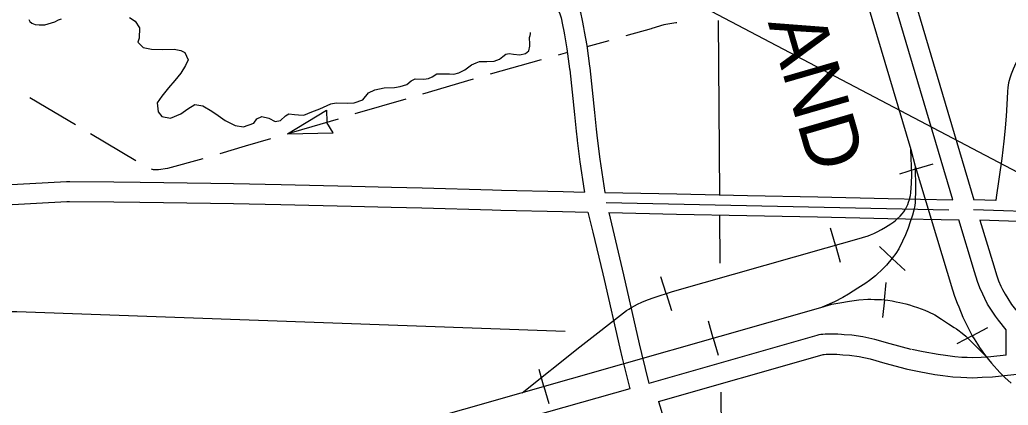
# Model space of a CAD drawing. Extents: x 1373094 to 1376427, y 1168361 to 1170494.
# Drawn here: x 1373679.1 to 1373802.5, y 1170075.4 to 1170123.5 of the extents above; entities that cross this region are included whole.
import ezdxf

# ---------------------------------------------------------------- set-up
doc = ezdxf.new("R2010")
doc.units = 0
doc.layers.add('R_Axis', color=7, linetype='Continuous')
doc.layers.add('R_Draft', color=7, linetype='Continuous')

msp = doc.modelspace()

# ---------------------------------------------------------------- linework, layer by layer
at = {"layer": 'R_Axis'}
for p, q in [((1373712.5, 1170109.25), (1373717.38, 1170112.23)), ((1373717.38, 1170112.23), (1373717.42, 1170110.71)), ((1373718.22, 1170109.39), (1373717.43, 1170110.69)), ((1373712.5, 1170109.25), (1373718.22, 1170109.39)), ((1373791.02, 1170104.89), (1373788.92, 1170104.25)), ((1373791.02, 1170104.89), (1373793.13, 1170105.52)), ((1373780.95, 1170095.36), (1373780.34, 1170097.48)), ((1373780.95, 1170095.36), (1373781.55, 1170093.25)), ((1373788.04, 1170093.7), (1373786.43, 1170095.2)), ((1373789.66, 1170092.21), (1373788.04, 1170093.7)), ((1373759.79, 1170089.32), (1373759.12, 1170091.41)), ((1373787.05, 1170088.54), (1373787.27, 1170090.73)), ((1373759.79, 1170089.32), (1373760.46, 1170087.22)), ((1373787.05, 1170088.54), (1373786.82, 1170086.35)), ((1373765.69, 1170083.77), (1373765.09, 1170085.89)), ((1373798.03, 1170084.07), (1373799.97, 1170085.1)), ((1373765.69, 1170083.77), (1373766.29, 1170081.66)), ((1373798.03, 1170084.07), (1373796.08, 1170083.05)), ((1373744.54, 1170077.73), (1373743.93, 1170079.85)), ((1373744.54, 1170077.73), (1373745.14, 1170075.62))]:
    msp.add_line(p, q, dxfattribs=at)
for points in [[(1373784.43, 1170127.18), (1373790.37, 1170107.3), (1373790.91, 1170105.25), (1373795.57, 1170089.79), (1373795.81, 1170089), (1373796.14, 1170088.13), (1373796.33, 1170087.66), (1373796.87, 1170086.38), (1373797.01, 1170086.06), (1373797.28, 1170085.54), (1373797.46, 1170085.16), (1373798.07, 1170083.99), (1373798.25, 1170083.68), (1373798.67, 1170083), (1373798.94, 1170082.6), (1373799.26, 1170082.14), (1373799.57, 1170081.73), (1373800.07, 1170081.1), (1373800.45, 1170080.64), (1373801.48, 1170079.47), (1373801.76, 1170079.18), (1373802.08, 1170078.87), (1373802.87, 1170078.17)], [(1373784.43, 1170127.18), (1373790.37, 1170107.3), (1373790.91, 1170105.25), (1373795.57, 1170089.79), (1373795.81, 1170089), (1373796.14, 1170088.13), (1373796.33, 1170087.66), (1373796.87, 1170086.38), (1373797.01, 1170086.06), (1373797.28, 1170085.54), (1373797.46, 1170085.16), (1373798.07, 1170083.99), (1373798.25, 1170083.68), (1373798.67, 1170083), (1373798.94, 1170082.6), (1373799.26, 1170082.14), (1373799.57, 1170081.73), (1373800.07, 1170081.1), (1373800.45, 1170080.64), (1373801.48, 1170079.47), (1373801.76, 1170079.18), (1373802.08, 1170078.87), (1373802.87, 1170078.17)], [(1373795.6, 1170101.04), (1373788, 1170126.75)], [(1373790.4, 1170127.45), (1373798.21, 1170101.02)], [(1373748.16, 1170126.5), (1373748.57, 1170125.75), (1373748.85, 1170125.14), (1373749.09, 1170124.39), (1373749.31, 1170123.4), (1373749.48, 1170122.55), (1373749.56, 1170122.05), (1373749.88, 1170120.28), (1373750.24, 1170117.69), (1373750.25, 1170117.51)], [(1373745.97, 1170125.3), (1373746.34, 1170124.63), (1373746.51, 1170124.24), (1373746.68, 1170123.74), (1373746.86, 1170122.88), (1373747.02, 1170122.09), (1373747.1, 1170121.63), (1373747.41, 1170119.89), (1373747.75, 1170117.38), (1373747.77, 1170117.24)], [(1373680.22, 1170123.53), (1373680.34, 1170123.28), (1373680.6, 1170123.07), (1373681, 1170122.92), (1373681.5, 1170122.87), (1373682.22, 1170122.87), (1373683.45, 1170123.23), (1373683.93, 1170123.48), (1373684.29, 1170123.62)], [(1373692.77, 1170123.78), (1373693.51, 1170123.33), (1373694.05, 1170122.51), (1373693.98, 1170121.19), (1373693.81, 1170120.69), (1373694.49, 1170120.02), (1373695.51, 1170119.84), (1373696.93, 1170119.8), (1373698.36, 1170119.84), (1373699.18, 1170119.66), (1373699.69, 1170119.4), (1373700.1, 1170118.51), (1373699.77, 1170117.78), (1373699.18, 1170116.84), (1373698.44, 1170115.9), (1373697.67, 1170114.99), (1373696.82, 1170113.98), (1373696.25, 1170113.13), (1373696.38, 1170112), (1373696.83, 1170111.43), (1373697.92, 1170111.24), (1373699.2, 1170111.77), (1373700.08, 1170112.38), (1373700.95, 1170112.91), (1373701.96, 1170112.75), (1373703.05, 1170112.1), (1373703.86, 1170111.54), (1373704.73, 1170110.93), (1373705.96, 1170110.3), (1373707.03, 1170110.13), (1373708.3, 1170110.61), (1373708.7, 1170111.15), (1373709.29, 1170111.42), (1373710.18, 1170111.23), (1373710.97, 1170110.79), (1373711.65, 1170110.91), (1373712.25, 1170111.51), (1373712.69, 1170111.78), (1373713.37, 1170111.66), (1373713.87, 1170111.63), (1373714.55, 1170111.59), (1373715.54, 1170112.01), (1373716.54, 1170112.38), (1373717.94, 1170113), (1373718.6, 1170113.12), (1373719.98, 1170113.1), (1373720.83, 1170113.14), (1373721.92, 1170113.51), (1373722.64, 1170114.38), (1373723.41, 1170114.77), (1373724.57, 1170115.02), (1373725.86, 1170115.06), (1373726.58, 1170115.17), (1373727.4, 1170115.43), (1373727.97, 1170115.89), (1373728.44, 1170116.13), (1373729.54, 1170116.09), (1373730.14, 1170116.19), (1373730.58, 1170116.39), (1373731.17, 1170116.76), (1373732.75, 1170116.74), (1373733.28, 1170116.69), (1373733.91, 1170116.89), (1373734.65, 1170117.27), (1373735.49, 1170117.86), (1373736.09, 1170118.13), (1373736.48, 1170118.29), (1373737.41, 1170118.28), (1373738.34, 1170118.35)], [(1373761.15, 1170123.13), (1373761.02, 1170123.11), (1373759.53, 1170122.85), (1373758, 1170122.4), (1373757.94, 1170122.38)], [(1373766.31, 1170123.4), (1373766.45, 1170101.64)], [(1373738.34, 1170118.35), (1373738.97, 1170118.6), (1373739.39, 1170118.9), (1373739.76, 1170119.22), (1373740.19, 1170119.29), (1373740.73, 1170119.22), (1373741.53, 1170119.14), (1373742.24, 1170119.28), (1373742.64, 1170119.63), (1373742.76, 1170120.2), (1373742.76, 1170120.62), (1373742.73, 1170121.1), (1373742.73, 1170121.28), (1373742.82, 1170121.55), (1373742.85, 1170121.74), (1373742.84, 1170121.81), (1373742.88, 1170121.89)], [(1373757.94, 1170122.38), (1373754.77, 1170121.48)], [(1373752.65, 1170120.89), (1373749.9, 1170120.11)], [(1373747.47, 1170119.42), (1373746.3, 1170119.09)], [(1373744.18, 1170118.49), (1373737.83, 1170116.7)], [(1373803.94, 1170118.97), (1373803.78, 1170118.68), (1373803.48, 1170118.1), (1373803.14, 1170117.34), (1373802.9, 1170116.69), (1373802.73, 1170116.21), (1373802.57, 1170115.61), (1373802.48, 1170115.05), (1373802.41, 1170114.53), (1373802.4, 1170113.67), (1373802.26, 1170111.45), (1373802.19, 1170110.52), (1373802.13, 1170109.96)], [(1373747.77, 1170117.24), (1373748.37, 1170111.66), (1373748.58, 1170109.59), (1373748.68, 1170108.52)], [(1373750.25, 1170117.51), (1373750.86, 1170111.92), (1373751.07, 1170109.83), (1373751.17, 1170108.74)], [(1373735.72, 1170116.09), (1373729.38, 1170114.22)], [(1373686.02, 1170110.38), (1373682.39, 1170112.53), (1373680.35, 1170113.75)], [(1373727.27, 1170113.6), (1373720.94, 1170111.74)], [(1373718.83, 1170111.11), (1373713.26, 1170109.47), (1373712.5, 1170109.25)], [(1373802.13, 1170109.96), (1373801.97, 1170108.34), (1373801.74, 1170106.18), (1373801.01, 1170101.3)], [(1373693.59, 1170105.9), (1373687.92, 1170109.26)], [(1373710.39, 1170108.63), (1373707.22, 1170107.71)], [(1373748.68, 1170108.52), (1373748.69, 1170108.45), (1373749.02, 1170105.78), (1373749.56, 1170102.21), (1373749.59, 1170102)], [(1373751.17, 1170108.74), (1373751.17, 1170108.71), (1373751.5, 1170106.12), (1373752.13, 1170101.94)], [(1373707.22, 1170107.71), (1373704.06, 1170106.78)], [(1373741.8, 1170076.95), (1373749.01, 1170082.67), (1373754.84, 1170087.21), (1373755.12, 1170087.39), (1373755.46, 1170087.6), (1373755.85, 1170087.82), (1373756.22, 1170088.02), (1373756.76, 1170088.27), (1373757.49, 1170088.57), (1373758.3, 1170088.84), (1373760.58, 1170089.57), (1373779.78, 1170095.03), (1373783.6, 1170096.13), (1373785.01, 1170096.54), (1373785.33, 1170096.66), (1373785.73, 1170096.83), (1373786.17, 1170097.05), (1373786.69, 1170097.32), (1373787.18, 1170097.61), (1373787.84, 1170098.04), (1373788.23, 1170098.3), (1373788.42, 1170098.46), (1373788.66, 1170098.65), (1373789.01, 1170098.98), (1373789.28, 1170099.27), (1373789.49, 1170099.54), (1373789.68, 1170099.85), (1373789.83, 1170100.12), (1373789.97, 1170100.44), (1373790.08, 1170100.75), (1373790.19, 1170101.05), (1373790.25, 1170101.29), (1373790.31, 1170101.58), (1373790.36, 1170101.9), (1373790.44, 1170103.09), (1373790.46, 1170104.16), (1373790.37, 1170107.3)], [(1373741.8, 1170076.95), (1373749.01, 1170082.67), (1373754.84, 1170087.21), (1373755.12, 1170087.39), (1373755.46, 1170087.6), (1373755.85, 1170087.82), (1373756.22, 1170088.02), (1373756.76, 1170088.27), (1373757.49, 1170088.57), (1373758.3, 1170088.84), (1373760.58, 1170089.57), (1373779.78, 1170095.03), (1373783.6, 1170096.13), (1373785.01, 1170096.54), (1373785.33, 1170096.66), (1373785.73, 1170096.83), (1373786.17, 1170097.05), (1373786.69, 1170097.32), (1373787.18, 1170097.61), (1373787.84, 1170098.04), (1373788.23, 1170098.3), (1373788.42, 1170098.46), (1373788.66, 1170098.65), (1373789.01, 1170098.98), (1373789.28, 1170099.27), (1373789.49, 1170099.54), (1373789.68, 1170099.85), (1373789.83, 1170100.12), (1373789.97, 1170100.44), (1373790.08, 1170100.75), (1373790.19, 1170101.05), (1373790.25, 1170101.29), (1373790.31, 1170101.58), (1373790.36, 1170101.9), (1373790.44, 1170103.09), (1373790.46, 1170104.16), (1373790.37, 1170107.3)], [(1373701.94, 1170106.16), (1373697.54, 1170104.94), (1373696.41, 1170104.79), (1373695.8, 1170104.79), (1373695.53, 1170104.86)], [(1373790.91, 1170105.25), (1373790.95, 1170102.41), (1373790.88, 1170100.69), (1373790.85, 1170100.34), (1373790.74, 1170099.74), (1373790.57, 1170099.12), (1373790.29, 1170098.3), (1373790.01, 1170097.51), (1373789.67, 1170096.68), (1373789.31, 1170095.87), (1373788.85, 1170094.92), (1373788.49, 1170094.34), (1373788.04, 1170093.73), (1373787.31, 1170092.87), (1373786.89, 1170092.45), (1373785.95, 1170091.56), (1373785.19, 1170090.95), (1373784.75, 1170090.64), (1373783.75, 1170089.99), (1373782.56, 1170089.27), (1373781.85, 1170088.86), (1373780.81, 1170088.31), (1373779.27, 1170087.65)], [(1373790.91, 1170105.25), (1373790.95, 1170102.41), (1373790.88, 1170100.69), (1373790.85, 1170100.34), (1373790.74, 1170099.74), (1373790.57, 1170099.12), (1373790.29, 1170098.3), (1373790.01, 1170097.51), (1373789.67, 1170096.68), (1373789.31, 1170095.87), (1373788.85, 1170094.92), (1373788.49, 1170094.34), (1373788.04, 1170093.73), (1373787.31, 1170092.87), (1373786.89, 1170092.45), (1373785.95, 1170091.56), (1373785.19, 1170090.95), (1373784.75, 1170090.64), (1373783.75, 1170089.99), (1373782.56, 1170089.27), (1373781.85, 1170088.86), (1373780.81, 1170088.31), (1373779.27, 1170087.65)], [(1373676.46, 1170102.86), (1373684.91, 1170103.32), (1373685.32, 1170103.32)], [(1373685.32, 1170103.32), (1373690.84, 1170103.26), (1373694.12, 1170103.22)], [(1373694.12, 1170103.22), (1373702.92, 1170103.12)], [(1373702.92, 1170103.12), (1373705.79, 1170103.08), (1373711.74, 1170102.94)], [(1373711.74, 1170102.94), (1373720.53, 1170102.73)], [(1373720.53, 1170102.73), (1373725.51, 1170102.61), (1373729.34, 1170102.51)], [(1373729.34, 1170102.51), (1373738.13, 1170102.27)], [(1373738.13, 1170102.27), (1373739.23, 1170102.24), (1373746.93, 1170102.06)], [(1373746.93, 1170102.06), (1373749.59, 1170102)], [(1373752.13, 1170101.94), (1373761.14, 1170101.76)], [(1373676.59, 1170100.37), (1373684.96, 1170100.82), (1373685.3, 1170100.82)], [(1373685.3, 1170100.82), (1373690.81, 1170100.76), (1373694.09, 1170100.72)], [(1373694.09, 1170100.72), (1373702.89, 1170100.62)], [(1373752.31, 1170100.69), (1373795.09, 1170099.8)], [(1373761.14, 1170101.76), (1373769.94, 1170101.57)], [(1373769.94, 1170101.57), (1373778.73, 1170101.39)], [(1373778.73, 1170101.39), (1373787.53, 1170101.2)], [(1373787.53, 1170101.2), (1373795.6, 1170101.04)], [(1373800.96, 1170100.93), (1373798.21, 1170101.02)], [(1373801.01, 1170101.3), (1373800.96, 1170100.93)], [(1373702.89, 1170100.62), (1373705.75, 1170100.58), (1373711.68, 1170100.44)], [(1373711.68, 1170100.44), (1373720.47, 1170100.23)], [(1373720.47, 1170100.23), (1373725.45, 1170100.11), (1373729.27, 1170100.01)], [(1373729.27, 1170100.01), (1373738.07, 1170099.77)], [(1373738.07, 1170099.77), (1373739.16, 1170099.74), (1373746.87, 1170099.56)], [(1373746.87, 1170099.56), (1373750, 1170099.49)], [(1373750, 1170099.49), (1373750.65, 1170096.98), (1373751.88, 1170091.81), (1373752.05, 1170091.09)], [(1373752.64, 1170099.43), (1373761.09, 1170099.26)], [(1373752.64, 1170099.43), (1373754.32, 1170092.38), (1373754.49, 1170091.65)], [(1373847.31, 1170096.54), (1373838.1, 1170097.89), (1373836.59, 1170098.07), (1373834.06, 1170098.24), (1373823.2, 1170098.75), (1373816.78, 1170099.09), (1373811.6, 1170099.26), (1373808.15, 1170099.44), (1373798.2, 1170099.77)], [(1373761.09, 1170099.26), (1373769.88, 1170099.07)], [(1373766.47, 1170099.14), (1373766.51, 1170093.12)], [(1373769.88, 1170099.07), (1373778.68, 1170098.89)], [(1373778.68, 1170098.89), (1373787.48, 1170098.7)], [(1373787.48, 1170098.7), (1373796.35, 1170098.52)], [(1373802.27, 1170084.8), (1373801.3, 1170086.02), (1373800.91, 1170086.52), (1373800.34, 1170087.37), (1373799.94, 1170088.03), (1373799.58, 1170088.72), (1373799.33, 1170089.24), (1373798.99, 1170090.03), (1373798.7, 1170090.85), (1373798.31, 1170092.04), (1373796.35, 1170098.52)], [(1373806.12, 1170098.26), (1373798.97, 1170098.5)], [(1373798.97, 1170098.5), (1373800.7, 1170092.79), (1373801.07, 1170091.66), (1373801.32, 1170090.94), (1373801.61, 1170090.26), (1373801.81, 1170089.84), (1373802.12, 1170089.27), (1373802.45, 1170088.71), (1373802.94, 1170087.98), (1373803.27, 1170087.56), (1373803.65, 1170087.08), (1373804, 1170086.67), (1373804.31, 1170086.34), (1373804.58, 1170086.05), (1373804.81, 1170085.84), (1373805.1, 1170085.6), (1373805.35, 1170085.41), (1373809.6, 1170082.46)], [(1373752.05, 1170091.09), (1373754.01, 1170082.51)], [(1373754.49, 1170091.65), (1373756.45, 1170083.07)], [(1373591.87, 1170034.32), (1373741.71, 1170076.93), (1373779.13, 1170087.61), (1373780.5, 1170087.99), (1373781.5, 1170088.18), (1373782.7, 1170088.4), (1373783.85, 1170088.54), (1373784.99, 1170088.62), (1373785.36, 1170088.62), (1373785.81, 1170088.61), (1373786.39, 1170088.6), (1373786.7, 1170088.58), (1373787.1, 1170088.54), (1373787.48, 1170088.5), (1373788.04, 1170088.41), (1373788.53, 1170088.32), (1373788.98, 1170088.23), (1373789.73, 1170088.05), (1373790.17, 1170087.92), (1373790.66, 1170087.78), (1373791.18, 1170087.61), (1373792.09, 1170087.27), (1373792.55, 1170087.07), (1373793.34, 1170086.66), (1373794.2, 1170086.15), (1373795.08, 1170085.57), (1373795.78, 1170085.11), (1373796.05, 1170084.92), (1373796.22, 1170084.81)], [(1373591.87, 1170034.32), (1373741.71, 1170076.93), (1373779.13, 1170087.61), (1373780.5, 1170087.99), (1373781.5, 1170088.18), (1373782.7, 1170088.4), (1373783.85, 1170088.54), (1373784.99, 1170088.62), (1373785.36, 1170088.62), (1373785.81, 1170088.61), (1373786.39, 1170088.6), (1373786.7, 1170088.58), (1373787.1, 1170088.54), (1373787.48, 1170088.5), (1373788.04, 1170088.41), (1373788.53, 1170088.32), (1373788.98, 1170088.23), (1373789.73, 1170088.05), (1373790.17, 1170087.92), (1373790.66, 1170087.78), (1373791.18, 1170087.61), (1373792.09, 1170087.27), (1373792.55, 1170087.07), (1373793.34, 1170086.66), (1373794.2, 1170086.15), (1373795.08, 1170085.57), (1373795.78, 1170085.11), (1373796.05, 1170084.92), (1373796.22, 1170084.81), (1373796.76, 1170084.41), (1373797.21, 1170084.03), (1373797.78, 1170083.49), (1373799.82, 1170081.42)], [(1373619.08, 1170087.11), (1373678.71, 1170087.1), (1373747.2, 1170084.66)], [(1373796.22, 1170084.81), (1373796.76, 1170084.41), (1373797.21, 1170084.03), (1373797.78, 1170083.49), (1373799.82, 1170081.42)], [(1373802.27, 1170081.65), (1373802.27, 1170084.8)], [(1373790.41, 1170082.36), (1373787.78, 1170083.07), (1373785.88, 1170083.59), (1373784.36, 1170083.93), (1373782.97, 1170084.14), (1373782.03, 1170084.2), (1373781.7, 1170084.23), (1373781.25, 1170084.26), (1373780.82, 1170084.28), (1373780.04, 1170084.27), (1373779.66, 1170084.25), (1373779.35, 1170084.23), (1373779.1, 1170084.21), (1373778.86, 1170084.17), (1373778.6, 1170084.1), (1373757.65, 1170078.12)], [(1373754.01, 1170082.51), (1373754.3, 1170081.26), (1373755.25, 1170077.44)], [(1373756.45, 1170083.07), (1373756.73, 1170081.84), (1373757.65, 1170078.12)], [(1373802.27, 1170081.65), (1373800.34, 1170081.44), (1373799.15, 1170081.37), (1373798.06, 1170081.33), (1373797.4, 1170081.34), (1373796.73, 1170081.37), (1373795.85, 1170081.43), (1373794.67, 1170081.59), (1373793.77, 1170081.71), (1373791.88, 1170082.06), (1373790.46, 1170082.35)], [(1373758.86, 1170075.87), (1373779.27, 1170081.69), (1373779.41, 1170081.73), (1373779.54, 1170081.74), (1373779.8, 1170081.76), (1373780.11, 1170081.77), (1373780.77, 1170081.78), (1373781.11, 1170081.76), (1373781.5, 1170081.74), (1373781.85, 1170081.7), (1373782.71, 1170081.65), (1373783.9, 1170081.47), (1373785.28, 1170081.17), (1373787.12, 1170080.66), (1373789.77, 1170079.95)], [(1373789.72, 1170079.96), (1373791.4, 1170079.61), (1373793.37, 1170079.24), (1373794.34, 1170079.11), (1373795.6, 1170078.94), (1373796.59, 1170078.88), (1373797.33, 1170078.84), (1373798.09, 1170078.83), (1373799.27, 1170078.88), (1373800.54, 1170078.95), (1373808.51, 1170079.8), (1373811.38, 1170080.12), (1373811.85, 1170080.16), (1373812.23, 1170080.18), (1373812.98, 1170080.19), (1373813.46, 1170080.17), (1373814.01, 1170080.14), (1373814.79, 1170080.07), (1373815.72, 1170079.96), (1373816.62, 1170079.84), (1373817.79, 1170079.6), (1373819.16, 1170079.24), (1373820.45, 1170078.84), (1373823.03, 1170077.97)], [(1373755.25, 1170077.44), (1373631.72, 1170042.54)], [(1373766.63, 1170077.03), (1373766.83, 1170052.35)], [(1373758.86, 1170075.87), (1373761.03, 1170068.66)]]:
    msp.add_lwpolyline(points, dxfattribs=at)
at = {"layer": 'R_Draft'}
msp.add_line((1373526.32, 1170250.36), (1374006.35, 1169997.87), dxfattribs=at)

# ---------------------------------------------------------------- texts
at = {"layer": 'R_Axis'}
msp.add_text('AND', height=7.04, rotation=286.1842, dxfattribs=at).set_placement((1373772.48, 1170123.17))

doc.saveas('drawing.dxf')
